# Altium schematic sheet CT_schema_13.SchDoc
size 278 x 170 mm
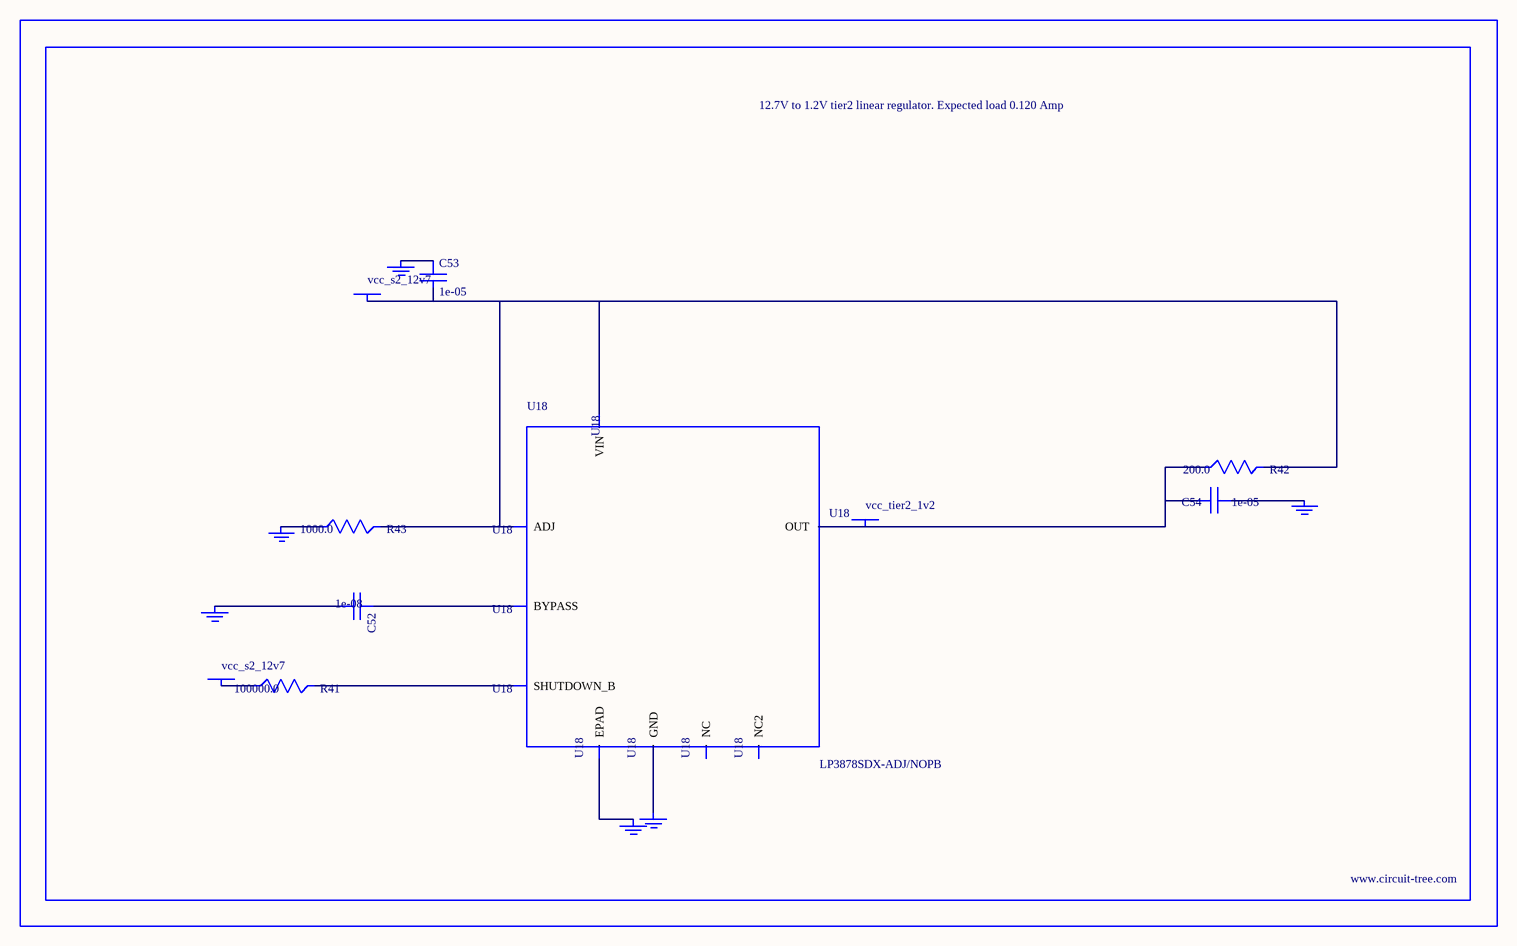
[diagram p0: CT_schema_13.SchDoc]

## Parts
BORDER12  (no value)
C52  1e-08  [C0402]
C53  1e-05  [C1210]
C54  1e-05  [C0805]
GND_INSTANCE_12_0  (no value)
GND_INSTANCE_12_1  (no value)
GND_INSTANCE_12_2  (no value)
GND_INSTANCE_12_3  (no value)
GND_INSTANCE_12_4  (no value)
GND_INSTANCE_12_5  (no value)
POWER_INSTANCE_12_0  vcc_s2_12v7
POWER_INSTANCE_12_1  vcc_s2_12v7
POWER_INSTANCE_12_2  vcc_tier2_1v2
R41  100000.0  [R0603]
R42  200.0  [R0603]
R43  1000.0  [R0603]
U18  LP3878SDX-ADJ/NOPB  [WSON-8]

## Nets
NetC52_1: C52.1 U18.1(BYPASS)
NetC52_2: C52.2 GND_INSTANCE_12_0.0(GND)
NetC53_1: C53.1 GND_INSTANCE_12_1.0(GND)
NetC53_2: C53.2 POWER_INSTANCE_12_0.0(PWR) R42.2 R43.2 U18.4(VIN) U18.6(ADJ)
NetC54_1: C54.1 GND_INSTANCE_12_2.0(GND)
NetC54_2: C54.2 POWER_INSTANCE_12_2.0(PWR) R42.1 U18.5(OUT)
NetGND_INSTANCE_12_3_0: GND_INSTANCE_12_3.0(GND) R43.1
NetGND_INSTANCE_12_4_0: GND_INSTANCE_12_4.0(GND) U18.PAD(EPAD)
NetGND_INSTANCE_12_5_0: GND_INSTANCE_12_5.0(GND) U18.3(GND)
NetPOWER_INSTANCE_12_1_0: POWER_INSTANCE_12_1.0(PWR) R41.1
NetR41_2: R41.2 U18.8(SHUTDOWN_B)

Not connected (* = marked no-connect by the designer): U18 2(NC) 7(NC2)

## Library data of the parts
BORDER12 = BORDER_PAGE12
C52 = C0402C103K3RAC
C53 = C1210C106K5PACTU
C54 = GRM219R60J106ME19D
GND_INSTANCE_12_0-GND_INSTANCE_12_5 = GND
POWER_INSTANCE_12_0-POWER_INSTANCE_12_2 = PWR
R41 = RC0603JR-07100KL
R42 = RC0603JR-07200RL
R43 = RC0603JR-071KL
